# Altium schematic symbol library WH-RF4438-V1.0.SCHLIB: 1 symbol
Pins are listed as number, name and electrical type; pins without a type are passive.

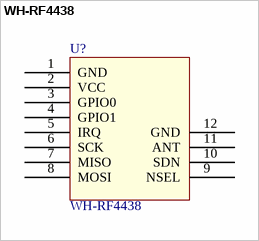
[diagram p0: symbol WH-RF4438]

## WH-RF4438
designator U?
pins: 1 GND, 2 VCC, 3 GPIO0, 4 GPIO1, 5 IRQ, 6 SCK, 7 MISO, 8 MOSI, 9 NSEL, 10 SDN, 11 ANT, 12 GND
